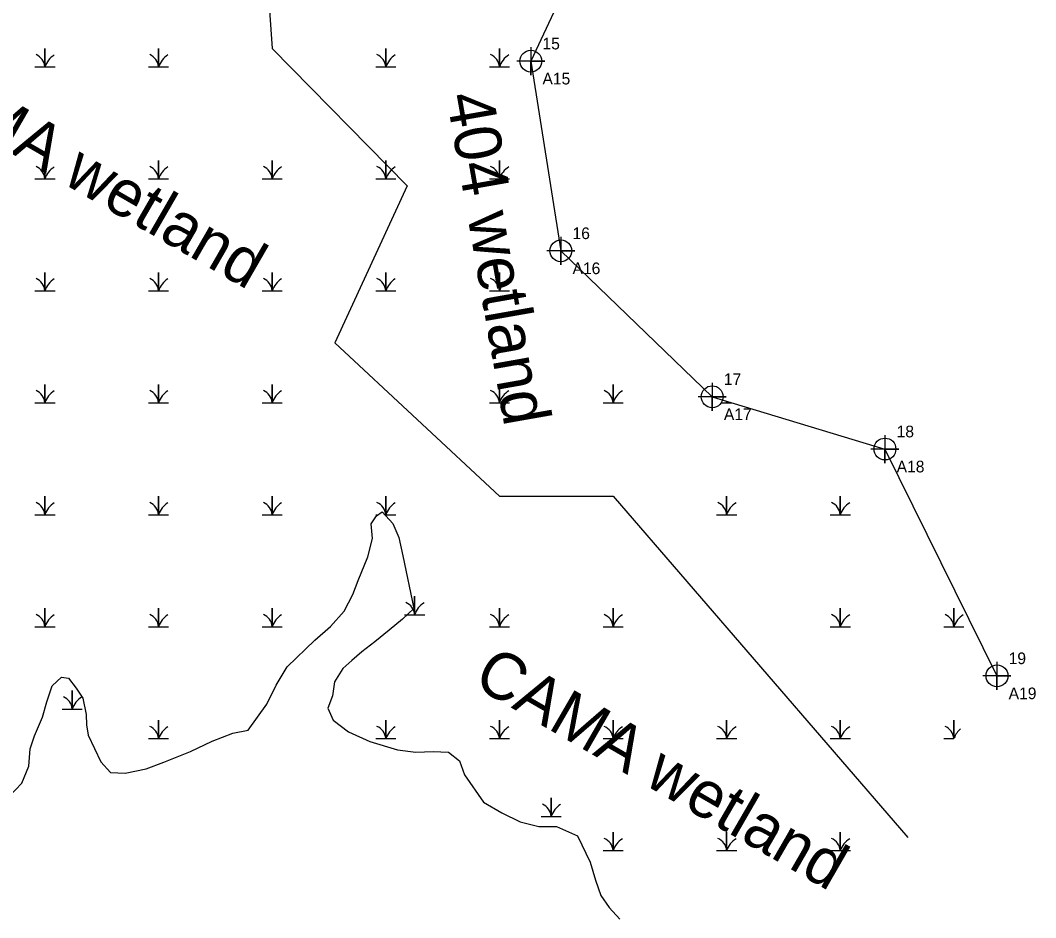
# Model space of a CAD drawing. Extents: x 2678633 to 2679425, y 623836 to 624637.
# Drawn here: x 2679208.1 to 2679425.3, y 624164.5 to 624356.4 of the extents above; entities that cross this region are included whole.
import ezdxf

# ---------------------------------------------------------------- set-up
doc = ezdxf.new("R2010")
doc.units = 0
for name, color, linetype in [('Exist Environmental Wetland Boundary', 7, 'Continuous'), ('Exist Environmental Wetland Boundary Cogo Comment', 7, 'Continuous'), ('Exist Environmental Wetland Boundary Cogo Number', 7, 'Continuous'), ('Exist Environmental Wetland Boundary Cogo Point CELL', 7, 'Continuous'), ('Exist Environmental Wetland Boundary Text', 7, 'Continuous'), ('Exist Hydro Jurisdictional Stream or Body of Water NEU Mitigable', 7, 'Continuous'), ('Exist Hydro Swamp or Marsh', 7, 'Continuous')]:
    doc.layers.add(name, color=color, linetype=linetype)

msp = doc.modelspace()

# ---------------------------------------------------------------- linework, layer by layer
at = {"layer": 'Exist Environmental Wetland Boundary'}
for points in [[(2678996.94, 624177.71), (2679033.89, 624182.51), (2679071.36, 624253.6), (2679114.38, 624321.81), (2679163.39, 624374.56), (2679217.13, 624423.71), (2679286.14, 624470.62), (2679307.52, 624474.8), (2679321.51, 624489.84), (2679302.84, 624456.53), (2679292.78, 624438.21), (2679296.8, 624418.87), (2679319.66, 624396.04), (2679331.43, 624377.88), (2679317.29, 624347.71), (2679323.72, 624307.13), (2679356.11, 624275.91), (2679393.07, 624264.72), (2679417.04, 624216.21)], [(2679264.64, 624456.01), (2679283.2, 624418.1), (2679258.89, 624394.15), (2679261.95, 624350.41), (2679290.83, 624321), (2679275.38, 624287.41), (2679310.58, 624254.61), (2679334.89, 624254.61), (2679397.97, 624181.63)]]:
    msp.add_lwpolyline(points, dxfattribs=at)
at = {"layer": 'Exist Environmental Wetland Boundary Cogo Point CELL'}
for points in [[(2679317.29, 624350.71), (2679317.29, 624344.71), (2679317.29, 624347.71), (2679320.29, 624347.71), (2679314.29, 624347.71)], [(2679323.72, 624310.13), (2679323.72, 624304.13), (2679323.72, 624307.13), (2679326.72, 624307.13), (2679320.72, 624307.13)], [(2679356.11, 624278.91), (2679356.11, 624272.91), (2679356.11, 624275.91), (2679359.11, 624275.91), (2679353.11, 624275.91)], [(2679393.07, 624267.72), (2679393.07, 624261.72), (2679393.07, 624264.72), (2679396.07, 624264.72), (2679390.07, 624264.72)], [(2679417.04, 624219.21), (2679417.04, 624213.21), (2679417.04, 624216.21), (2679420.04, 624216.21), (2679414.04, 624216.21)]]:
    msp.add_lwpolyline(points, dxfattribs=at)
for centre in [(2679317.29, 624347.71), (2679323.72, 624307.13), (2679356.11, 624275.91), (2679393.07, 624264.72), (2679417.04, 624216.21)]:
    msp.add_circle(centre, 2.34, dxfattribs=at)
at = {"layer": 'Exist Hydro Jurisdictional Stream or Body of Water NEU Mitigable'}
msp.add_lwpolyline([(2679205.68, 624190.38), (2679208.4, 624193.26), (2679209.87, 624196.91), (2679210.18, 624200.59), (2679211.07, 624203.34), (2679212.77, 624207.34), (2679213.72, 624210.63), (2679214.87, 624214.05), (2679216.89, 624215.91), (2679218.36, 624215.7), (2679220.03, 624213.56), (2679221.44, 624211.42), (2679222.17, 624207.96), (2679222.22, 624205.71), (2679222.56, 624203.54), (2679225.32, 624197.78), (2679227.34, 624195.53), (2679230.49, 624195.42), (2679234.97, 624196.35), (2679238.8, 624197.77), (2679244.47, 624199.99), (2679249.08, 624202.23), (2679253.52, 624203.97), (2679256.84, 624204.59), (2679260.82, 624210.15), (2679262.81, 624214.24), (2679265.13, 624218.14), (2679271.08, 624223.84), (2679274.43, 624226.77), (2679277.35, 624230.06), (2679279.18, 624233.62), (2679280.35, 624236.59), (2679282.44, 624241.64), (2679283.41, 624245.57), (2679283.14, 624248.72), (2679284.28, 624250.47), (2679285.49, 624251.28), (2679287.76, 624248.78), (2679289.04, 624245.83), (2679289.94, 624241.91), (2679292.27, 624230.64), (2679289.81, 624228.35), (2679286.95, 624225.99), (2679283.91, 624223.47), (2679281.1, 624221.33), (2679279.02, 624219.49), (2679277.08, 624217.77), (2679275.32, 624214.9), (2679274.87, 624211.93), (2679273.85, 624209.29), (2679275.02, 624206.71), (2679278.25, 624204.23), (2679282.88, 624202.16), (2679288.76, 624200.37), (2679292.71, 624199.85), (2679296.4, 624200.01), (2679299.66, 624199.88), (2679302.06, 624198), (2679303.13, 624195.04), (2679307.15, 624189.2), (2679311.07, 624186.89), (2679315.01, 624185), (2679319, 624183.95), (2679322.78, 624183.97), (2679327.29, 624181.98), (2679329.99, 624176.33), (2679331.1, 624172.53), (2679332.28, 624169.19), (2679334.08, 624166.66), (2679336.33, 624164.17)], dxfattribs=at)
at = {"layer": 'Exist Hydro Swamp or Marsh'}
for p, q in [((2679292.44, 624231.07), (2679292.44, 624231.07)), ((2679219.17, 624210.89), (2679219.17, 624210.89)), ((2679321.65, 624187.92), (2679321.65, 624187.92))]:
    msp.add_line(p, q, dxfattribs=at)
for points in [[(2679211.18, 624346.47), (2679213.33, 624346.47), (2679213.33, 624350.41), (2679213.33, 624346.47), (2679215.48, 624346.47)], [(2679235.49, 624346.47), (2679237.64, 624346.47), (2679237.64, 624350.41), (2679237.64, 624346.47), (2679239.79, 624346.47)], [(2679284.11, 624346.47), (2679286.26, 624346.47), (2679286.26, 624350.41), (2679286.26, 624346.47), (2679288.42, 624346.47)], [(2679308.43, 624346.47), (2679310.58, 624346.47), (2679310.58, 624350.41), (2679310.58, 624346.47), (2679312.73, 624346.47)], [(2679211.18, 624322.52), (2679213.33, 624322.52), (2679213.33, 624326.46), (2679213.33, 624322.52), (2679215.48, 624322.52)], [(2679235.49, 624322.52), (2679237.64, 624322.52), (2679237.64, 624326.46), (2679237.64, 624322.52), (2679239.79, 624322.52)], [(2679259.8, 624322.52), (2679261.95, 624322.52), (2679261.95, 624326.46), (2679261.95, 624322.52), (2679264.1, 624322.52)], [(2679284.11, 624322.52), (2679286.26, 624322.52), (2679286.26, 624326.46), (2679286.26, 624322.52), (2679288.42, 624322.52)], [(2679308.43, 624322.52), (2679310.58, 624322.52), (2679310.58, 624326.46), (2679310.58, 624322.52), (2679312.73, 624322.52)], [(2679211.18, 624298.57), (2679213.33, 624298.57), (2679213.33, 624302.51), (2679213.33, 624298.57), (2679215.48, 624298.57)], [(2679235.49, 624298.57), (2679237.64, 624298.57), (2679237.64, 624302.51), (2679237.64, 624298.57), (2679239.79, 624298.57)], [(2679259.8, 624298.57), (2679261.95, 624298.57), (2679261.95, 624302.51), (2679261.95, 624298.57), (2679264.1, 624298.57)], [(2679284.11, 624298.57), (2679286.26, 624298.57), (2679286.26, 624302.51), (2679286.26, 624298.57), (2679288.42, 624298.57)], [(2679308.43, 624298.57), (2679310.58, 624298.57), (2679310.58, 624302.51), (2679310.58, 624298.57), (2679312.73, 624298.57)], [(2679211.18, 624274.62), (2679213.33, 624274.62), (2679213.33, 624278.56), (2679213.33, 624274.62), (2679215.48, 624274.62)], [(2679235.49, 624274.62), (2679237.64, 624274.62), (2679237.64, 624278.56), (2679237.64, 624274.62), (2679239.79, 624274.62)], [(2679259.8, 624274.62), (2679261.95, 624274.62), (2679261.95, 624278.56), (2679261.95, 624274.62), (2679264.1, 624274.62)], [(2679308.43, 624274.62), (2679310.58, 624274.62), (2679310.58, 624278.56), (2679310.58, 624274.62), (2679312.73, 624274.62)], [(2679332.74, 624274.62), (2679334.89, 624274.62), (2679334.89, 624278.56), (2679334.89, 624274.62), (2679337.04, 624274.62)], [(2679358.03, 624274.62), (2679359.2, 624274.62), (2679359.2, 624274.97)], [(2679359.2, 624274.97), (2679359.2, 624274.62), (2679360.37, 624274.62)], [(2679211.18, 624250.67), (2679213.33, 624250.67), (2679213.33, 624254.61), (2679213.33, 624250.67), (2679215.48, 624250.67)], [(2679235.49, 624250.67), (2679237.64, 624250.67), (2679237.64, 624254.61), (2679237.64, 624250.67), (2679239.79, 624250.67)], [(2679259.8, 624250.67), (2679261.95, 624250.67), (2679261.95, 624254.61), (2679261.95, 624250.67), (2679264.1, 624250.67)], [(2679286.05, 624250.67), (2679286.26, 624250.67), (2679286.26, 624254.61), (2679286.26, 624250.67), (2679288.42, 624250.67)], [(2679357.05, 624250.67), (2679359.2, 624250.67), (2679359.2, 624254.61), (2679359.2, 624250.67), (2679361.35, 624250.67)], [(2679381.36, 624250.67), (2679383.51, 624250.67), (2679383.51, 624254.61), (2679383.51, 624250.67), (2679385.67, 624250.67)], [(2679284.11, 624250.67), (2679284.57, 624250.67)], [(2679290.29, 624229.29), (2679292.44, 624229.29), (2679292.44, 624233.24), (2679292.44, 624229.29), (2679294.59, 624229.29)], [(2679211.18, 624226.72), (2679213.33, 624226.72), (2679213.33, 624230.66), (2679213.33, 624226.72), (2679215.48, 624226.72)], [(2679235.49, 624226.72), (2679237.64, 624226.72), (2679237.64, 624230.66), (2679237.64, 624226.72), (2679239.79, 624226.72)], [(2679259.8, 624226.72), (2679261.95, 624226.72), (2679261.95, 624230.66), (2679261.95, 624226.72), (2679264.1, 624226.72)], [(2679308.43, 624226.72), (2679310.58, 624226.72), (2679310.58, 624230.66), (2679310.58, 624226.72), (2679312.73, 624226.72)], [(2679332.74, 624226.72), (2679334.89, 624226.72), (2679334.89, 624230.66), (2679334.89, 624226.72), (2679337.04, 624226.72)], [(2679381.36, 624226.72), (2679383.51, 624226.72), (2679383.51, 624230.66), (2679383.51, 624226.72), (2679385.67, 624226.72)], [(2679405.68, 624226.72), (2679407.83, 624226.72), (2679407.83, 624230.66), (2679407.83, 624226.72), (2679409.98, 624226.72)], [(2679217.02, 624209.11), (2679219.17, 624209.11), (2679219.17, 624213.05), (2679219.17, 624209.11), (2679221.32, 624209.11)], [(2679235.49, 624202.77), (2679237.64, 624202.77), (2679237.64, 624206.71), (2679237.64, 624202.77), (2679239.79, 624202.77)], [(2679284.11, 624202.77), (2679286.26, 624202.77), (2679286.26, 624206.71), (2679286.26, 624202.77), (2679288.42, 624202.77)], [(2679308.43, 624202.77), (2679310.58, 624202.77), (2679310.58, 624206.71), (2679310.58, 624202.77), (2679312.73, 624202.77)], [(2679332.74, 624202.77), (2679334.89, 624202.77), (2679334.89, 624206.71), (2679334.89, 624202.77), (2679337.04, 624202.77)], [(2679357.05, 624202.77), (2679359.2, 624202.77), (2679359.2, 624206.71), (2679359.2, 624202.77), (2679361.35, 624202.77)], [(2679381.36, 624202.77), (2679383.51, 624202.77), (2679383.51, 624206.71), (2679383.51, 624202.77), (2679385.67, 624202.77)], [(2679407.83, 624202.84), (2679407.83, 624206.71), (2679407.83, 624202.84)], [(2679405.68, 624202.77), (2679407.78, 624202.77)], [(2679319.5, 624186.14), (2679321.65, 624186.14), (2679321.65, 624190.08), (2679321.65, 624186.14), (2679323.8, 624186.14)], [(2679332.74, 624178.82), (2679334.89, 624178.82), (2679334.89, 624182.76), (2679334.89, 624178.82), (2679337.04, 624178.82)], [(2679357.05, 624178.82), (2679359.2, 624178.82), (2679359.2, 624182.76), (2679359.2, 624178.82), (2679361.35, 624178.82)], [(2679381.36, 624178.82), (2679383.51, 624178.82), (2679383.51, 624182.76), (2679383.51, 624178.82), (2679385.67, 624178.82)]]:
    msp.add_lwpolyline(points, dxfattribs=at)
for centre, radius, start, end in [((2679210.26, 624346.25), 3.07, 4.1403, 67.535), ((2679217.89, 624344.95), 4.81, 122.1274, 161.6222), ((2679234.57, 624346.25), 3.07, 4.1403, 67.535), ((2679242.2, 624344.95), 4.81, 122.1274, 161.6222), ((2679283.2, 624346.25), 3.07, 4.1403, 67.535), ((2679290.83, 624344.95), 4.81, 122.1274, 161.6222), ((2679307.51, 624346.25), 3.07, 4.1403, 67.535), ((2679315.14, 624344.95), 4.81, 122.1274, 161.6222), ((2679210.26, 624322.3), 3.07, 4.1403, 67.535), ((2679217.89, 624321), 4.81, 122.1274, 161.6222), ((2679234.57, 624322.3), 3.07, 4.1403, 67.535), ((2679242.2, 624321), 4.81, 122.1274, 161.6222), ((2679258.89, 624322.3), 3.07, 4.1403, 67.535), ((2679266.51, 624321), 4.81, 122.1274, 161.6222), ((2679283.2, 624322.3), 3.07, 4.1403, 67.535), ((2679290.83, 624321), 4.81, 122.1274, 161.6222), ((2679307.51, 624322.3), 3.07, 4.1403, 67.535), ((2679315.14, 624321), 4.81, 122.1274, 161.6222), ((2679210.26, 624298.35), 3.07, 4.1403, 67.535), ((2679217.89, 624297.05), 4.81, 122.1274, 161.6222), ((2679234.57, 624298.35), 3.07, 4.1403, 67.535), ((2679242.2, 624297.05), 4.81, 122.1274, 161.6222), ((2679258.89, 624298.35), 3.07, 4.1403, 67.535), ((2679266.51, 624297.05), 4.81, 122.1274, 161.6222), ((2679283.2, 624298.35), 3.07, 4.1403, 67.535), ((2679290.83, 624297.05), 4.81, 122.1274, 161.6222), ((2679307.51, 624298.35), 3.07, 4.1403, 67.535), ((2679315.14, 624297.05), 4.81, 122.1274, 161.6222), ((2679210.26, 624274.4), 3.07, 4.1403, 67.535), ((2679217.89, 624273.1), 4.81, 122.1274, 161.6222), ((2679234.57, 624274.4), 3.07, 4.1403, 67.535), ((2679242.2, 624273.1), 4.81, 122.1274, 161.6222), ((2679258.89, 624274.4), 3.07, 4.1403, 67.535), ((2679266.51, 624273.1), 4.81, 122.1274, 161.6222), ((2679307.51, 624274.4), 3.07, 4.1403, 67.535), ((2679315.14, 624273.1), 4.81, 122.1274, 161.6222), ((2679331.82, 624274.4), 3.07, 4.1403, 67.535), ((2679339.45, 624273.1), 4.81, 122.1274, 161.6222), ((2679356.14, 624274.4), 3.07, 4.1403, 11.0919), ((2679363.76, 624273.1), 4.81, 157.5677, 161.6222), ((2679210.26, 624250.45), 3.07, 4.1403, 67.535), ((2679217.89, 624249.15), 4.81, 122.1274, 161.6222), ((2679234.57, 624250.45), 3.07, 4.1403, 67.535), ((2679242.2, 624249.15), 4.81, 122.1274, 161.6222), ((2679258.89, 624250.45), 3.07, 4.1403, 67.535), ((2679266.51, 624249.15), 4.81, 122.1274, 161.6222), ((2679283.2, 624250.45), 3.07, 4.1403, 67.535), ((2679290.83, 624249.15), 4.81, 122.1274, 161.6222), ((2679356.14, 624250.45), 3.07, 4.1403, 67.535), ((2679363.76, 624249.15), 4.81, 122.1274, 161.6222), ((2679380.45, 624250.45), 3.07, 4.1403, 67.535), ((2679388.08, 624249.15), 4.81, 122.1274, 161.6222), ((2679289.37, 624229.07), 3.07, 4.1403, 67.535), ((2679297, 624227.78), 4.81, 122.1274, 161.6222), ((2679210.26, 624226.5), 3.07, 4.1403, 67.535), ((2679217.89, 624225.2), 4.81, 122.1274, 161.6222), ((2679234.57, 624226.5), 3.07, 4.1403, 67.535), ((2679242.2, 624225.2), 4.81, 122.1274, 161.6222), ((2679258.89, 624226.5), 3.07, 4.1403, 67.535), ((2679266.51, 624225.2), 4.81, 122.1274, 161.6222), ((2679307.51, 624226.5), 3.07, 4.1403, 67.535), ((2679315.14, 624225.2), 4.81, 122.1274, 161.6222), ((2679331.82, 624226.5), 3.07, 4.1403, 67.535), ((2679339.45, 624225.2), 4.81, 122.1274, 161.6222), ((2679380.45, 624226.5), 3.07, 4.1403, 67.535), ((2679388.08, 624225.2), 4.81, 122.1274, 161.6222), ((2679404.76, 624226.5), 3.07, 4.1403, 67.535), ((2679412.39, 624225.2), 4.81, 122.1274, 161.6222), ((2679216.1, 624208.89), 3.07, 4.1403, 67.535), ((2679223.73, 624207.59), 4.81, 122.1274, 161.6222), ((2679234.57, 624202.55), 3.07, 4.1403, 67.535), ((2679242.2, 624201.25), 4.81, 122.1274, 161.6222), ((2679283.2, 624202.55), 3.07, 4.1403, 67.535), ((2679290.83, 624201.25), 4.81, 122.1274, 161.6222), ((2679307.51, 624202.55), 3.07, 4.1403, 67.535), ((2679315.14, 624201.25), 4.81, 122.1274, 161.6222), ((2679331.82, 624202.55), 3.07, 4.1403, 67.535), ((2679339.45, 624201.25), 4.81, 122.1274, 161.6222), ((2679356.14, 624202.55), 3.07, 4.1403, 67.535), ((2679363.76, 624201.25), 4.81, 122.1274, 161.6222), ((2679380.45, 624202.55), 3.07, 4.1403, 67.535), ((2679388.08, 624201.25), 4.81, 122.1274, 161.6222), ((2679404.76, 624202.55), 3.07, 5.3638, 67.535), ((2679412.39, 624201.25), 4.81, 131.1564, 159.7349), ((2679318.59, 624185.92), 3.07, 4.1403, 67.535), ((2679326.21, 624184.62), 4.81, 122.1274, 161.6222), ((2679331.82, 624178.6), 3.07, 4.1403, 67.535), ((2679339.45, 624177.3), 4.81, 122.1274, 161.6222), ((2679356.14, 624178.6), 3.07, 4.1403, 67.535), ((2679363.76, 624177.3), 4.81, 122.1274, 161.6222), ((2679380.45, 624178.6), 3.07, 4.1403, 67.535), ((2679388.08, 624177.3), 4.81, 122.1274, 161.6222)]:
    msp.add_arc(centre, radius, start, end, dxfattribs=at)

# ---------------------------------------------------------------- texts
at = {"layer": 'Exist Environmental Wetland Boundary Cogo Comment'}
for s, p in [('A15', (2679319.79, 624342.71)), ('A16', (2679326.22, 624302.13)), ('A17', (2679358.61, 624270.91)), ('A18', (2679395.57, 624259.72)), ('A19', (2679419.54, 624211.21))]:
    msp.add_text(s, height=2.5, dxfattribs=at).set_placement(p)
at = {"layer": 'Exist Environmental Wetland Boundary Cogo Number'}
for s, p in [('15', (2679319.79, 624350.21)), ('16', (2679326.22, 624309.63)), ('17', (2679358.61, 624278.41)), ('18', (2679395.57, 624267.22)), ('19', (2679419.54, 624218.71))]:
    msp.add_text(s, height=2.5, dxfattribs=at).set_placement(p)
at = {"layer": 'Exist Environmental Wetland Boundary Text'}
for s, rotation, p in [('CAMA wetland', 330, (2679180.16, 624342.91)), ('404 wetland', 280, (2679299.17, 624340.28)), ('CAMA wetland', 330, (2679304.59, 624214.29))]:
    msp.add_text(s, height=10, rotation=rotation, dxfattribs=at).set_placement(p)

doc.saveas('drawing.dxf')
